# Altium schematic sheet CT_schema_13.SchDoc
size 391 x 385 mm
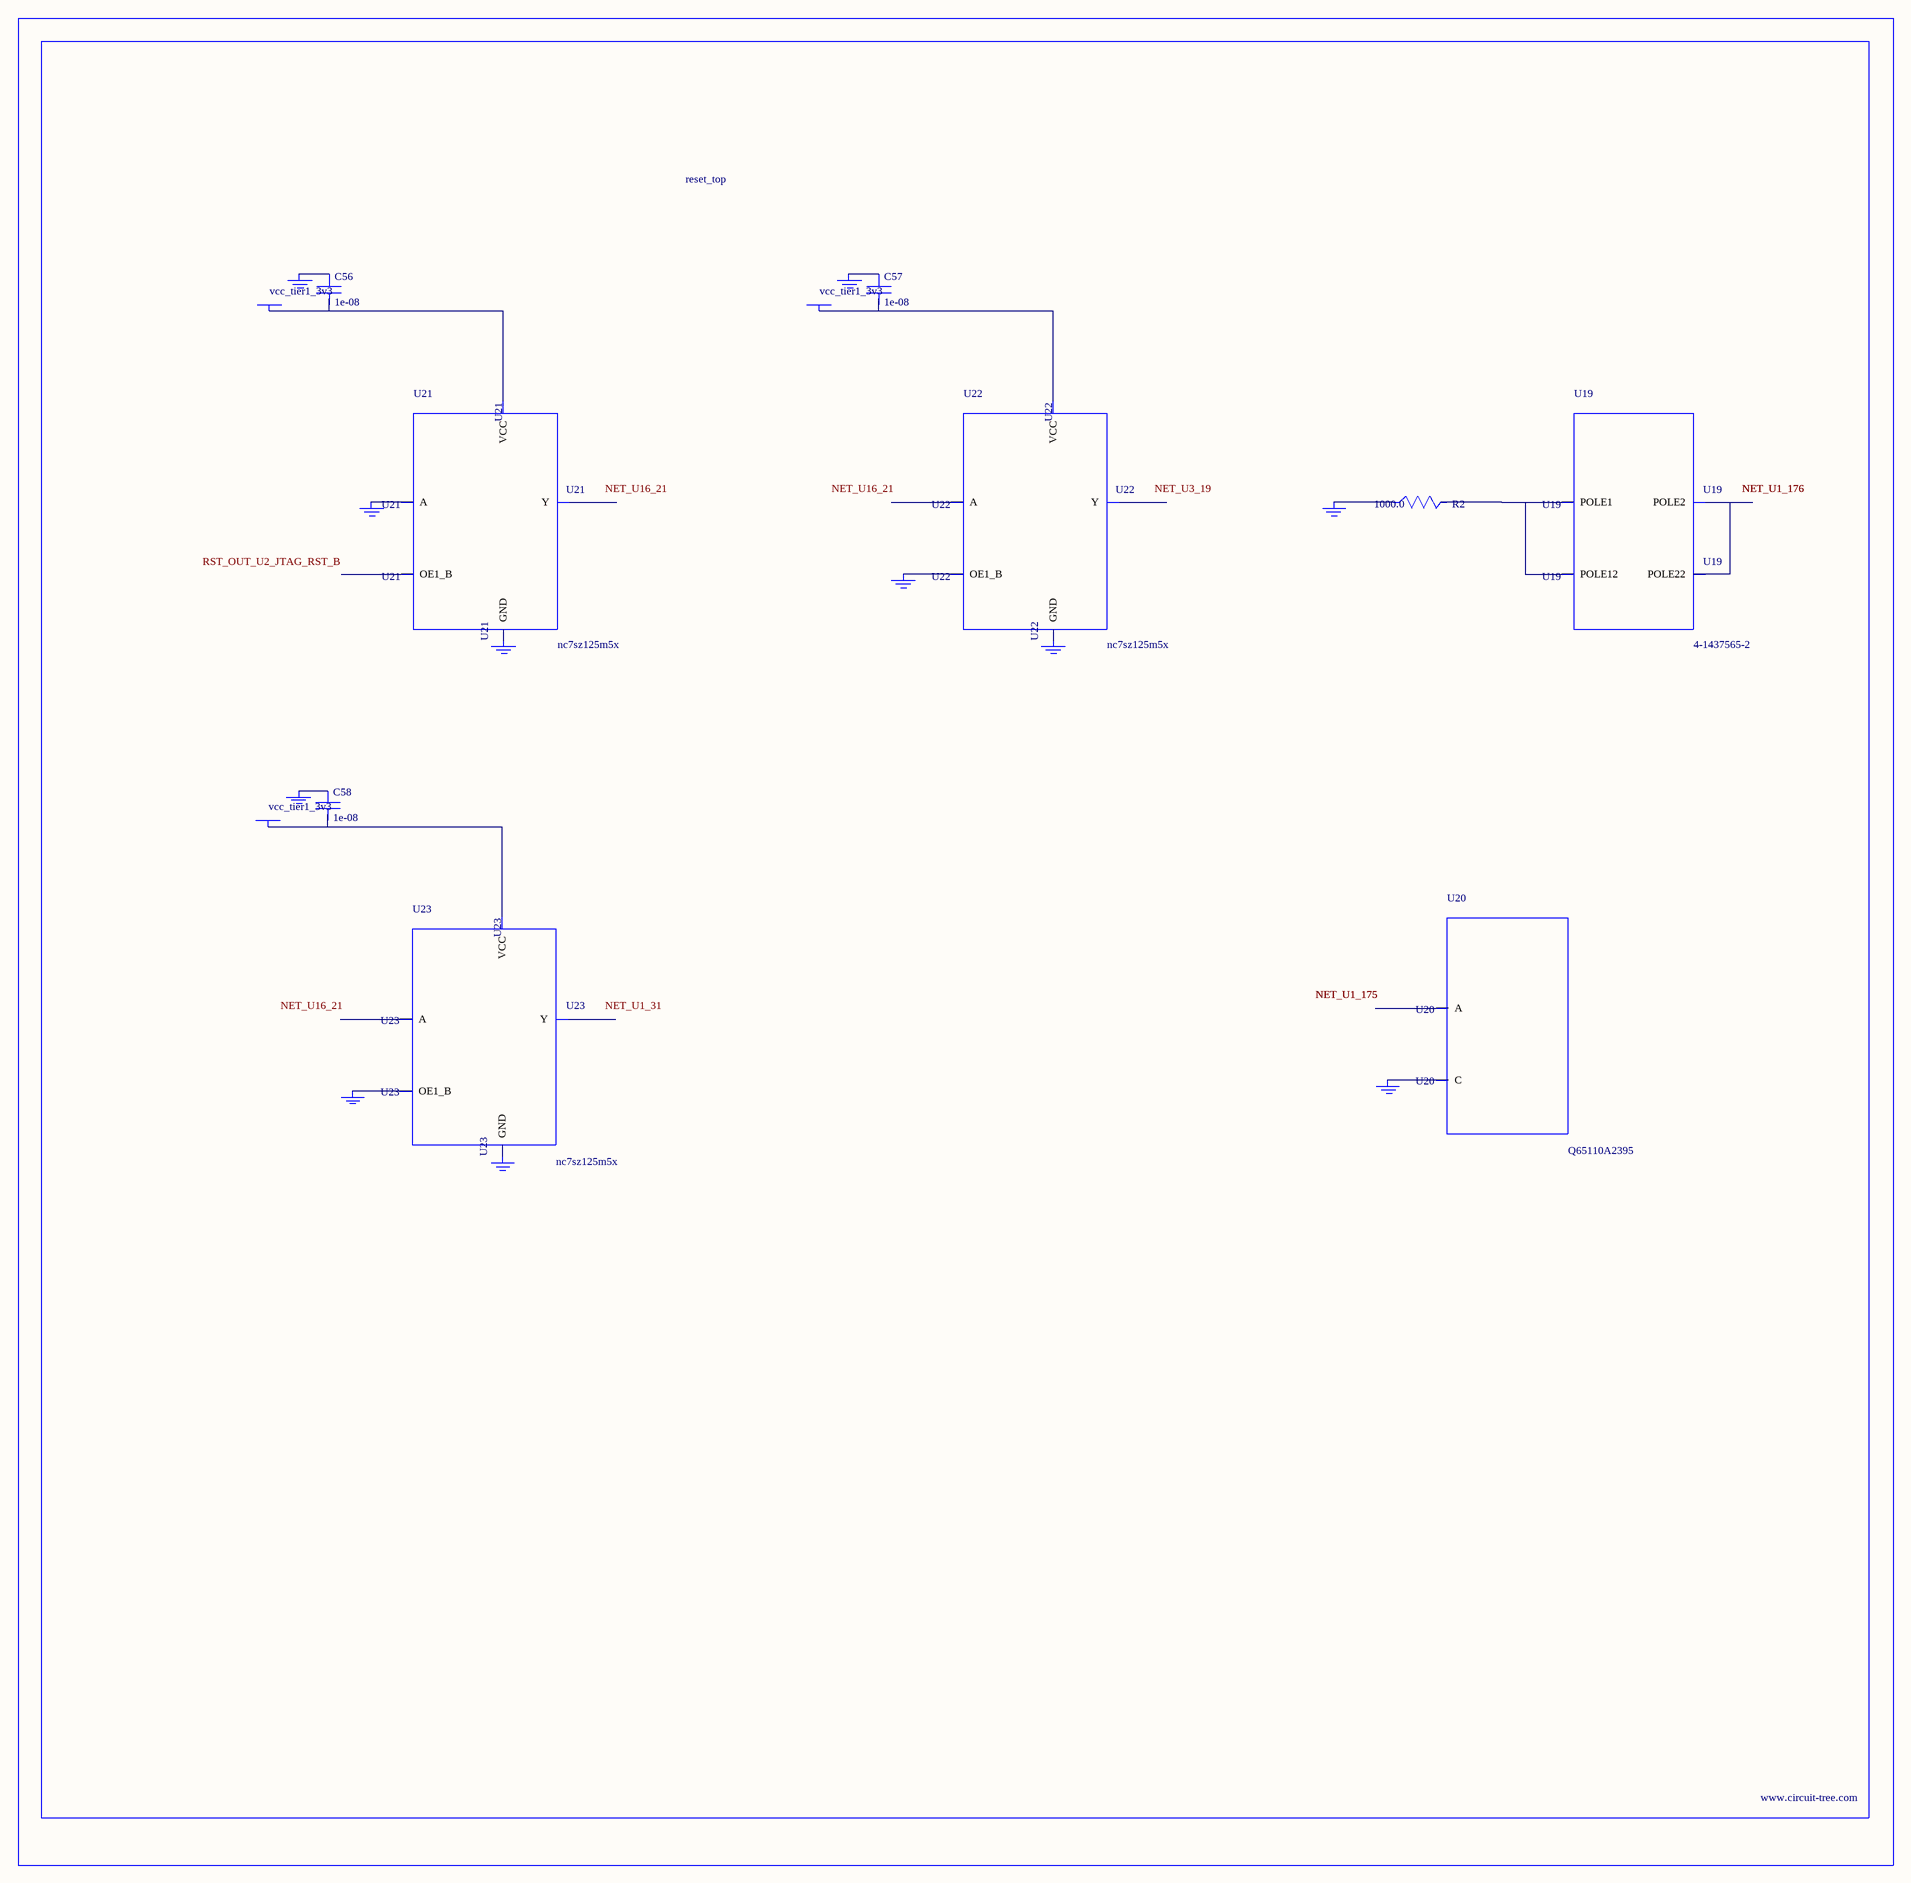
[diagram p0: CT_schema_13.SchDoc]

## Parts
BORDER12  (no value)
C56  1e-08  [C0402]
C57  1e-08  [C0402]
C58  1e-08  [C0402]
GND_INSTANCE_12_0  (no value)
GND_INSTANCE_12_1  (no value)
GND_INSTANCE_12_2  (no value)
GND_INSTANCE_12_3  (no value)
GND_INSTANCE_12_4  (no value)
GND_INSTANCE_12_5  (no value)
GND_INSTANCE_12_6  (no value)
GND_INSTANCE_12_7  (no value)
GND_INSTANCE_12_8  (no value)
GND_INSTANCE_12_9  (no value)
GND_INSTANCE_12_10  (no value)
POWER_INSTANCE_12_0  vcc_tier1_3v3
POWER_INSTANCE_12_1  vcc_tier1_3v3
POWER_INSTANCE_12_2  vcc_tier1_3v3
R2  1000.0  [R0603]
U19  4-1437565-2  [SW_4-1437565-2]
U20  Q65110A2395  [LGM67K-G1J2-24-Z]
U21  nc7sz125m5x  [NC7SZ125M5X]
U22  nc7sz125m5x  [NC7SZ125M5X]
U23  nc7sz125m5x  [NC7SZ125M5X]

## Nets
NetC56_1: C56.1 GND_INSTANCE_12_2.0(GND)
NetC56_2: C56.2 POWER_INSTANCE_12_0.0(PWR) U21.5(VCC)
NetC57_1: C57.1 GND_INSTANCE_12_5.0(GND)
NetC57_2: C57.2 POWER_INSTANCE_12_1.0(PWR) U22.5(VCC)
NetC58_1: C58.1 GND_INSTANCE_12_8.0(GND)
NetC58_2: C58.2 POWER_INSTANCE_12_2.0(PWR) U23.5(VCC)
NetGND_INSTANCE_12_0_0: GND_INSTANCE_12_0.0(GND) R2.1
NetGND_INSTANCE_12_1_0: GND_INSTANCE_12_1.0(GND) U20.C
NetGND_INSTANCE_12_3_0: GND_INSTANCE_12_3.0(GND) U21.2(A)
NetGND_INSTANCE_12_4_0: GND_INSTANCE_12_4.0(GND) U21.3(GND)
NetGND_INSTANCE_12_6_0: GND_INSTANCE_12_6.0(GND) U22.1(OE1_B)
NetGND_INSTANCE_12_7_0: GND_INSTANCE_12_7.0(GND) U22.3(GND)
NetGND_INSTANCE_12_9_0: GND_INSTANCE_12_9.0(GND) U23.1(OE1_B)
NetGND_INSTANCE_12_10_0: GND_INSTANCE_12_10.0(GND) U23.3(GND)
NetR2_2: R2.2 U19.1(POLE1) U19.2(POLE12)
NetU19_3: U19.3(POLE2) U19.4(POLE22)

Not connected (* = marked no-connect by the designer): U20 A; U21 1(OE1_B) 4(Y); U22 2(A) 4(Y); U23 2(A) 4(Y)

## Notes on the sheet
- Labels drawn without touching a wire or pin: NET_U1_31, NET_U3_19, NET_U16_21, RST_OUT_U2_JTAG_RST_B

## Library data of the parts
BORDER12 = BORDER_PAGE12
C56-C58 = C0402C103K3RAC
GND_INSTANCE_12_0-GND_INSTANCE_12_10 = GND
POWER_INSTANCE_12_0-POWER_INSTANCE_12_2 = PWR
R2 = RC0603JR-071KL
